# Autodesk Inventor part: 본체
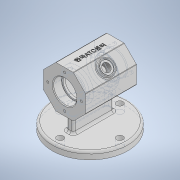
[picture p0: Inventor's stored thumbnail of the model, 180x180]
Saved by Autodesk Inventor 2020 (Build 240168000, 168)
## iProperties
Created: 2021-02
Part Number: 본체
Material: 일반
Document SubType Name: Modeling
Designer: USER
Density: 1 g/cm^3
Appearance: 기본값
Mass: 206.872 g
Surface Area: 501.684 cm^2
Volume: 206.872 cm^3
Author: USER
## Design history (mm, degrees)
sketch "스케치1" dims "d0" = 58
  geometry: L1 (12.012, 29)-(29, 12.012); L2 (29, 12.012)-(29, -12.012); L3 (29, -12.012)-(12.012, -29); L4 (12.012, -29)-(-12.012, -29); L5 (-12.012, -29)-(-29, -12.012); L6 (-29, -12.012)-(-29, 12.012); L7 (-29, 12.012)-(-12.012, 29); L8 (-12.012, 29)-(12.012, 29); 5 further points
  constraints: 16 end point, 2 coincident, 2 midpoint, 1 horizontal alignment, 1 vertical alignment, 19 other
extrude "돌출1" new body sketch "스케치1" distance "d1" = 70; taper "d2" = 0 deg
sketch "스케치2"
  geometry: C1 r 16 at (0, 0); 1 further point
  constraints: 1 centre point, 1 coincident
  dimensions: "d3" = 32 diameter of C1
extrude "돌출2" cut sketch "스케치2" distance "d4" = 12; taper "d5" = 0 deg
sketch "스케치3"
  geometry: L1 (-16, 58)-(16, 58) reference; L2 (12.012, 0)-(-12.012, 0) reference; L3 (0, 58)-(0, 0); L4 (14, 58)-(14, 55); L5 (14, 55)-(22, 55); L6 (22, 55)-(22, 15); L7 (22, 15)-(14, 15); L8 (14, 15)-(14, 12); L9 (14, 12)-(16, 12); L10 (16, 12)-(16, 0); L11 (29, 0)-(12.012, 0) reference
  constraints: 16 end point, 5 perpendicular, 2 point on line, 1 midpoint, 1 vertical
  dimensions: "d6" = 28 diameter of L4 L3; "d7" = 3 distance of L4.start L4.end; "d8" = 44 diameter of L6 L3; "d9" = 40 distance of L5.end L6.end; "d10" = 28 diameter of L8 L3; "d11" = 3 distance of L7.end L8.end; "d12" = 32 diameter of L10 L3
revolve "회전1" sketch "스케치3" stored, may be unused: angle "d13" = 90 deg
node "작업 평면1"
sketch "스케치4"
  geometry: C1 r 52 at (0, 35); 2 further points
  constraints: 1 centre point, 1 coincident, 1 vertical alignment
  dimensions: "d16" = 35 distance of point (0, 0) point (0, 35); "d17" = 104 diameter of C1
extrude "돌출3" join sketch "스케치4" distance "d18" = 10; taper "d19" = 0 deg
sketch "스케치5"
  geometry: L1 (2, -28)-(-2, -28); L2 (-5, -25)-(-5, 25); L3 (-2, 28)-(2, 28); L4 (5, 25)-(5, -25); L5 (5, -28)-(-5, 28); L6 (-5, -28)-(5, 28); C1 r 52 at (0, 0) reference; A1 r 3 centre (-2, 25) between (-2, 28) and (-5, 25); A2 r 3 centre (2, 25) between (5, 25) and (2, 28); A3 r 3 centre (2, -25) between (2, -28) and (5, -25); A4 r 3 centre (-2, -25) between (-5, -25) and (-2, -28); 1 further point
  constraints: 12 end point, 8 point on circle, 8 point on line, 8 tangent, 4 centre point, 3 equal radius, 2 midpoint, 2 parallel, 1 horizontal, 1 perpendicular
  dimensions: "d20" = 10 distance of L5.end L6.end; "d21" = 56 distance of L6.start L5.end; "d22" = 3 radius of A1
extrude "돌출4" join sketch "스케치5" stored distance "d23" = 10; taper "d24" = 0 deg
sketch "스케치7"
  geometry: L1 (0, 70)-(16.988, 70) reference; C1 r 10 at (-12.012, 35); 1 further point
  constraints: 1 centre point
  dimensions: "d26" = 20 diameter of C1; "d27" = 35 distance from line of C1.centre L1; "d28" = 29 horizontal distance of C1.centre L1.end
extrude "돌출5" join sketch "스케치7" distance "d29" = 5; taper "d30" = 0 deg
sketch "스케치8"
  geometry: C1 r 10 at (0, 0) reference; C2 r 8 at (0, 0); 1 further point
  constraints: 1 centre point, 1 coincident
  dimensions: "d31" = 16 diameter of C2
extrude "돌출6" cut sketch "스케치8" distance "d32" = 2; taper "d33" = 0 deg
sketch "스케치9"
  geometry: C1 r 8 at (0, 0) reference; 2 further points
  constraints: 1 coincident
hole "구멍1" sketch "스케치9" at (0, 0) diameter "d34" = 10.917; stored, may be unused: countersink angle "d38" = 90 deg, drill point angle "d40" = 0 deg; dims "d35" = 24, "d36" = 4, "d37" = 2, "d39" = 20
node "작업 평면2"
sketch "스케치11" dims "d41" = 82
  geometry: C1 r 52 at (0, 0) reference; C2 r 4.5 at (-41, 0); 2 further points
  constraints: 2 horizontal alignment, 1 centre point, 1 coincident, 2 other
  dimensions: "d42" = 9 diameter of C2
extrude "돌출7" cut sketch "스케치11" stored distance "d43" = 2; taper "d44" = 0 deg
fillet "모깎기1" dims "d48" = 1
fillet "모깎기2" dims "d49" = 3
fillet "모깎기3" dims "d50" = 0.3
chamfer "모따기1" distance "d51" = 1; stored, may be unused: second distance "d52" = 2, angle "d53" = 45 deg
fillet "모깎기4" dims "d54" = 3
fillet "모깎기5" dims "d55" = 3
fillet "모깎기6" dims "d56" = 3
sketch "스케치12"
  geometry: L1 (23.196, -70)-(0, -70) reference; L2 (-17.109, -70)-(-17.109, 0) reference; 2 further points
  constraints: 1 other
  dimensions: "d57" = 35 distance from line of point (11.891, -35) L1; "d58" = 29 distance from line of point (11.891, -35) L2
feature "엠보싱1" sketch "스케치12" dims "d6" = 28, "d7" = 3, "d8" = 44, "d9" = 40, "d10" = 28, "d11" = 3, "d12" = 32, "d59" = 0.5, "d60" = 0
chamfer "모따기2" distance "d61" = 1; stored, may be unused: second distance "d62" = 2, angle "d63" = 45 deg
sketch "스케치13"
  geometry: 2 further points
  constraints: 1 vertical alignment
  dimensions: "d64" = 23 distance of point (0, 0) point (0, 23)
hole "구멍2" sketch "스케치13" at (0, 23) diameter "d65" = 3.242; stored, may be unused: countersink angle "d69" = 90 deg, drill point angle "d71" = 118 deg; dims "d66" = 8, "d67" = 4, "d68" = 2, "d70" = 10
fillet "모깎기7" dims "d75" = 1
node "솔리드1"
pattern_circular "원형 패턴1" dims angle "d46" = 360 deg
pattern_circular "원형 패턴2" dims angle "d73" = 360 deg
mirror "미러1"
node "투영된 루프2"
feature "A9D066F2-1C7D-4E18-AEED-F7BC21143FA4" dims "d34" = 10.917, "d35" = 24, "d36" = 4, "d37" = 2, "d38" = 90 deg, "d39" = 20, "d40" = 0
other parameters: "d14" = -62
